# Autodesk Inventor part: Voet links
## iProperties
Created: 2007-06
Part Number: Voet links
Material: Steel
Document SubType Name: Modeling
Designer: Phil Trethewie
Author: Phil Trethewie
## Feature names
1. Derived Body1 [Tagging]
